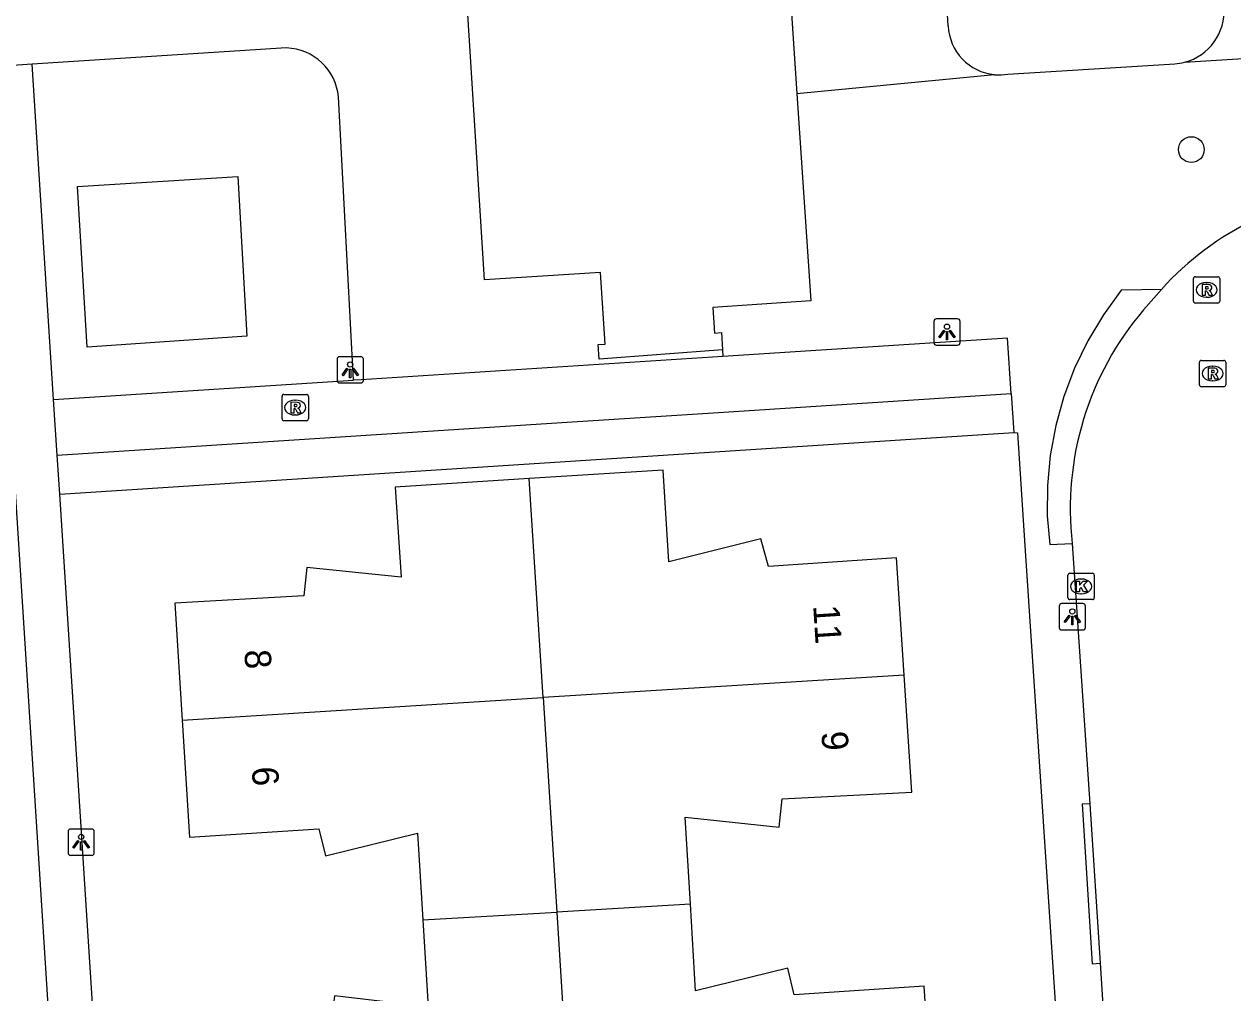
# Model space of a CAD drawing. Extents: x 159689 to 160786, y 387323 to 388339.
# Drawn here: x 160308.71 to 160354.58, y 387664.33 to 387701.1 of the extents above; entities that cross this region are included whole.
import ezdxf

# ---------------------------------------------------------------- set-up
doc = ezdxf.new("R2010")
doc.units = 0
for name, color, linetype in [('IMGEO_Boom', 7, 'Continuous'), ('IMGEO_Groenvoorziening', 7, 'Continuous'), ('IMGEO_Kolk', 7, 'Continuous'), ('IMGEO_Lichtpunt', 7, 'Continuous'), ('IMGEO_Pand', 7, 'Continuous'), ('IMGEO_Pand_nummerreeks', 7, 'Continuous'), ('IMGEO_Rijbaan_lokaal_open', 7, 'Continuous'), ('IMGEO_Rioolput', 7, 'Continuous'), ('IMGEO_Voetpad_open', 7, 'Continuous')]:
    doc.layers.add(name, color=color, linetype=linetype)

msp = doc.modelspace()

# ---------------------------------------------------------------- linework, layer by layer
at = {"layer": 'IMGEO_Boom'}
msp.add_circle((160353.01, 387696.335), 0.489, dxfattribs=at)
at = {"layer": 'IMGEO_Groenvoorziening'}
msp.add_lwpolyline([(160316.815, 387695.319), (160317.164, 387689.248), (160311.105, 387688.841), (160310.736, 387694.931), (160316.815, 387695.319)], dxfattribs=at)
at = {"layer": 'IMGEO_Kolk'}
for p, q in [((160348.327, 387679.327), (160348.327, 387680.179)), ((160348.402, 387680.253), (160349.254, 387680.253)), ((160348.815, 387680.033), (160348.84, 387680.033)), ((160349.328, 387680.179), (160349.328, 387679.327)), ((160349.254, 387679.253), (160348.402, 387679.253)), ((160348.838, 387679.473), (160348.813, 387679.473))]:
    msp.add_line(p, q, dxfattribs=at)
for points in [[(160348.327, 387679.327), (160348.327, 387680.179)], [(160348.402, 387680.253), (160349.254, 387680.253)], [(160349.328, 387680.179), (160349.328, 387679.327)], [(160348.648, 387679.953), (160348.771, 387679.953), (160348.771, 387679.802), (160348.901, 387679.953), (160349.065, 387679.953), (160348.919, 387679.802), (160349.072, 387679.553), (160348.92, 387679.553), (160348.835, 387679.717), (160348.771, 387679.65), (160348.771, 387679.553), (160348.648, 387679.553), (160348.648, 387679.953)], [(160349.254, 387679.253), (160348.402, 387679.253)]]:
    msp.add_lwpolyline(points, dxfattribs=at)
for centre, start, end in [((160348.404, 387680.177), 91.552, 178.448), ((160348.404, 387680.177), 91.552, 178.448), ((160349.252, 387680.177), 1.552, 88.448), ((160349.252, 387680.177), 1.552, 88.448), ((160348.404, 387679.329), 181.552, 268.448), ((160348.404, 387679.329), 181.552, 268.448), ((160349.252, 387679.329), 271.552, 358.448), ((160349.252, 387679.329), 271.552, 358.448)]:
    msp.add_arc(centre, 0.0765, start, end, dxfattribs=at)
for centre, major_axis, ratio, start_param, end_param in [((160348.814, 387679.753), (-0.387, 0.002), 0.722429, 4.712389, 7.853982), ((160348.839, 387679.753), (-0.39, 0.002), 0.717154, 1.570796, 4.712389)]:
    msp.add_ellipse(centre, major_axis=major_axis, ratio=ratio, start_param=start_param, end_param=end_param, dxfattribs=at)
at = {"layer": 'IMGEO_Lichtpunt'}
for p, q in [((160343.238, 387689.815), (160343.238, 387689.008)), ((160343.238, 387689.815), (160343.238, 387689.008)), ((160344.14, 387689.91), (160343.332, 387689.91)), ((160344.14, 387689.91), (160343.332, 387689.91)), ((160344.234, 387689.008), (160344.234, 387689.815)), ((160344.234, 387689.008), (160344.234, 387689.815)), ((160343.332, 387688.914), (160344.14, 387688.914)), ((160343.332, 387688.914), (160344.14, 387688.914)), ((160320.588, 387688.379), (160320.588, 387687.572)), ((160320.588, 387688.379), (160320.588, 387687.572)), ((160321.49, 387688.474), (160320.682, 387688.474)), ((160321.49, 387688.474), (160320.682, 387688.474)), ((160321.584, 387687.572), (160321.584, 387688.379)), ((160321.584, 387687.572), (160321.584, 387688.379)), ((160320.682, 387687.478), (160321.49, 387687.478)), ((160320.682, 387687.478), (160321.49, 387687.478)), ((160347.994, 387679.004), (160347.994, 387678.197)), ((160347.994, 387679.004), (160347.994, 387678.197)), ((160348.896, 387679.099), (160348.088, 387679.099)), ((160348.896, 387679.099), (160348.088, 387679.099)), ((160348.99, 387678.197), (160348.99, 387679.004)), ((160348.99, 387678.197), (160348.99, 387679.004)), ((160348.088, 387678.103), (160348.896, 387678.103)), ((160348.088, 387678.103), (160348.896, 387678.103)), ((160310.376, 387670.446), (160310.376, 387669.639)), ((160310.376, 387670.446), (160310.376, 387669.639)), ((160311.278, 387670.541), (160310.47, 387670.541)), ((160311.278, 387670.541), (160310.47, 387670.541)), ((160311.372, 387669.639), (160311.372, 387670.446)), ((160311.372, 387669.639), (160311.372, 387670.446)), ((160310.47, 387669.545), (160311.278, 387669.545)), ((160310.47, 387669.545), (160311.278, 387669.545))]:
    msp.add_line(p, q, dxfattribs=at)
for points in [[(160343.612, 387689.479), (160343.651, 387689.451), (160343.463, 387689.189), (160343.425, 387689.216), (160343.612, 387689.479)], [(160343.714, 387689.431), (160343.761, 387689.431), (160343.761, 387689.109), (160343.714, 387689.109), (160343.714, 387689.431)], [(160343.824, 387689.451), (160343.862, 387689.478), (160344.049, 387689.216), (160344.01, 387689.188), (160343.824, 387689.451)], [(160320.962, 387688.043), (160321.001, 387688.015), (160320.813, 387687.753), (160320.775, 387687.78), (160320.962, 387688.043)], [(160321.064, 387687.995), (160321.111, 387687.995), (160321.111, 387687.673), (160321.064, 387687.673), (160321.064, 387687.995)], [(160321.174, 387688.015), (160321.212, 387688.042), (160321.399, 387687.78), (160321.36, 387687.752), (160321.174, 387688.015)], [(160348.368, 387678.668), (160348.407, 387678.64), (160348.219, 387678.378), (160348.181, 387678.405), (160348.368, 387678.668)], [(160348.58, 387678.64), (160348.618, 387678.667), (160348.805, 387678.405), (160348.766, 387678.377), (160348.58, 387678.64)], [(160348.47, 387678.62), (160348.517, 387678.62), (160348.517, 387678.298), (160348.47, 387678.298), (160348.47, 387678.62)], [(160310.75, 387670.11), (160310.789, 387670.082), (160310.601, 387669.82), (160310.563, 387669.847), (160310.75, 387670.11)], [(160310.852, 387670.062), (160310.899, 387670.062), (160310.899, 387669.74), (160310.852, 387669.74), (160310.852, 387670.062)], [(160310.962, 387670.082), (160311, 387670.109), (160311.187, 387669.847), (160311.148, 387669.819), (160310.962, 387670.082)]]:
    msp.add_lwpolyline(points, dxfattribs=at)
for centre in [(160343.737, 387689.613), (160321.087, 387688.177), (160348.493, 387678.802), (160310.875, 387670.244)]:
    msp.add_circle(centre, 0.0994, dxfattribs=at)
for centre, start, end in [((160343.332, 387689.815), 90, 180), ((160343.332, 387689.815), 90, 180), ((160344.14, 387689.815), 0, 90), ((160344.14, 387689.815), 0, 90), ((160343.332, 387689.008), 180, 270), ((160343.332, 387689.008), 180, 270), ((160344.14, 387689.008), 270, 0), ((160344.14, 387689.008), 270, 360), ((160320.682, 387688.379), 90, 180), ((160320.682, 387688.379), 90, 180), ((160321.49, 387688.379), 0, 90), ((160321.49, 387688.379), 0, 90), ((160320.682, 387687.572), 180, 270), ((160320.682, 387687.572), 180, 270), ((160321.49, 387687.572), 270, 0), ((160321.49, 387687.572), 270, 360), ((160348.088, 387679.004), 90, 180), ((160348.088, 387679.004), 90, 180), ((160348.896, 387679.004), 0, 90), ((160348.896, 387679.004), 0, 90), ((160348.088, 387678.197), 180, 270), ((160348.088, 387678.197), 180, 270), ((160348.896, 387678.197), 270, 0), ((160348.896, 387678.197), 270, 360), ((160310.47, 387670.446), 90, 180), ((160310.47, 387670.446), 90, 180), ((160311.278, 387670.446), 0, 90), ((160311.278, 387670.446), 0, 90), ((160310.47, 387669.639), 180, 270), ((160310.47, 387669.639), 180, 270), ((160311.278, 387669.639), 270, 0), ((160311.278, 387669.639), 270, 360)]:
    msp.add_arc(centre, 0.0946, start, end, dxfattribs=at)
at = {"layer": 'IMGEO_Pand'}
for points in [[(160334.757, 387750.277), (160334.77, 387750.067), (160340.756, 387750.466), (160340.787, 387750), (160341.127, 387744.922), (160334.957, 387744.51), (160338.038, 387698.462)], [(160335.221, 387688.73), (160330.534, 387688.385), (160330.499, 387688.934), (160330.758, 387688.95), (160330.585, 387691.675), (160326.184, 387691.396), (160322.891, 387743.823), (160321.76, 387743.808), (160321.744, 387744.061), (160317.251, 387743.782), (160316.917, 387748.799)], [(160338.038, 387698.462), (160338.565, 387690.589), (160334.844, 387690.34), (160334.909, 387689.371), (160335.178, 387689.389), (160335.221, 387688.73)], [(160342.113, 387676.39), (160341.825, 387680.84), (160336.962, 387680.514), (160336.666, 387681.564), (160333.18, 387680.683), (160332.963, 387684.165), (160327.875, 387683.846)], [(160327.875, 387683.846), (160322.787, 387683.526), (160323.023, 387680.104), (160319.445, 387680.47), (160319.329, 387679.399), (160314.427, 387679.123), (160314.709, 387674.678)], [(160328.404, 387675.534), (160327.875, 387683.846)], [(160342.113, 387676.39), (160328.404, 387675.534)], [(160333.995, 387667.695), (160333.797, 387670.989), (160337.368, 387670.609), (160337.477, 387671.686), (160342.401, 387671.942), (160342.113, 387676.39)], [(160314.709, 387674.678), (160328.404, 387675.534)], [(160328.404, 387675.534), (160328.923, 387667.393)], [(160314.709, 387674.678), (160314.992, 387670.23), (160319.892, 387670.551), (160320.148, 387669.531), (160323.639, 387670.39), (160323.843, 387667.09)], [(160333.995, 387667.695), (160328.923, 387667.393)], [(160343.16, 387660.128), (160342.874, 387664.579), (160337.942, 387664.248), (160337.696, 387665.267), (160334.193, 387664.4), (160333.995, 387667.695)], [(160323.843, 387667.09), (160328.923, 387667.393)], [(160328.923, 387667.393), (160329.44, 387659.266)], [(160323.843, 387667.09), (160324.047, 387663.789), (160320.484, 387664.206), (160320.362, 387663.157), (160315.434, 387662.866), (160315.733, 387658.405)]]:
    msp.add_lwpolyline(points, dxfattribs=at)
at = {"layer": 'IMGEO_Rijbaan_lokaal_open'}
for points in [[(160307.332, 387699.465), (160310.545, 387649.137), (160306.196, 387648.893), (160305.351, 387661.608)], [(160351.878, 387691.025), (160351.194, 387690.247)], [(160348.492, 387681.386), (160349.163, 387671.503)], [(160349.163, 387671.503), (160349.552, 387665.446)], [(160349.552, 387665.446), (160350.062, 387657.509), (160350.161, 387655.978)]]:
    msp.add_lwpolyline(points, dxfattribs=at)
for centre, radius, start, end in [((160360.131, 387683.684), 11.046, 92.1396, 138.3478), ((160360.001, 387682.719), 11.586, 139.4777, 186.606)]:
    msp.add_arc(centre, radius, start, end, dxfattribs=at)
at = {"layer": 'IMGEO_Rioolput'}
for p, q in [((160353.164, 387691.51), (160354.016, 387691.51)), ((160353.089, 387690.584), (160353.089, 387691.436)), ((160353.577, 387691.29), (160353.602, 387691.29)), ((160354.09, 387691.436), (160354.09, 387690.584)), ((160353.6, 387690.73), (160353.575, 387690.73)), ((160354.016, 387690.51), (160353.164, 387690.51)), ((160353.392, 387688.335), (160354.244, 387688.335)), ((160353.317, 387687.409), (160353.317, 387688.261)), ((160353.805, 387688.115), (160353.83, 387688.115)), ((160354.318, 387688.261), (160354.318, 387687.409)), ((160353.828, 387687.555), (160353.803, 387687.555)), ((160318.497, 387686.116), (160318.497, 387686.968)), ((160318.572, 387687.042), (160319.424, 387687.042)), ((160319.498, 387686.968), (160319.498, 387686.116)), ((160354.244, 387687.335), (160353.392, 387687.335)), ((160318.985, 387686.822), (160319.01, 387686.822)), ((160319.424, 387686.042), (160318.572, 387686.042)), ((160319.008, 387686.262), (160318.983, 387686.262))]:
    msp.add_line(p, q, dxfattribs=at)
for points in [[(160353.164, 387691.51), (160354.016, 387691.51)], [(160353.089, 387690.584), (160353.089, 387691.436)], [(160353.678, 387691.208), (160353.426, 387691.21), (160353.426, 387690.81)], [(160353.604, 387691.129), (160353.55, 387691.129), (160353.55, 387691.048)], [(160353.55, 387691.048), (160353.602, 387691.048)], [(160354.09, 387691.436), (160354.09, 387690.584)], [(160353.426, 387690.81), (160353.55, 387690.81), (160353.55, 387690.972), (160353.561, 387690.972)], [(160353.608, 387690.943), (160353.679, 387690.81), (160353.819, 387690.81), (160353.754, 387690.936)], [(160354.016, 387690.51), (160353.164, 387690.51)], [(160353.392, 387688.335), (160354.244, 387688.335)], [(160353.317, 387687.409), (160353.317, 387688.261)], [(160353.906, 387688.033), (160353.654, 387688.035), (160353.654, 387687.635)], [(160353.832, 387687.954), (160353.778, 387687.954), (160353.778, 387687.873)], [(160353.778, 387687.873), (160353.83, 387687.873)], [(160354.318, 387688.261), (160354.318, 387687.409)], [(160353.654, 387687.635), (160353.778, 387687.635), (160353.778, 387687.797), (160353.789, 387687.797)], [(160353.836, 387687.768), (160353.907, 387687.635), (160354.047, 387687.635), (160353.982, 387687.761)], [(160318.497, 387686.116), (160318.497, 387686.968)], [(160318.572, 387687.042), (160319.424, 387687.042)], [(160319.498, 387686.968), (160319.498, 387686.116)], [(160354.244, 387687.335), (160353.392, 387687.335)], [(160319.086, 387686.74), (160318.834, 387686.742), (160318.834, 387686.342)], [(160318.834, 387686.342), (160318.958, 387686.342), (160318.958, 387686.504), (160318.969, 387686.504)], [(160319.012, 387686.661), (160318.958, 387686.661), (160318.958, 387686.58)], [(160318.958, 387686.58), (160319.01, 387686.58)], [(160319.016, 387686.475), (160319.087, 387686.342), (160319.227, 387686.342), (160319.162, 387686.468)], [(160319.424, 387686.042), (160318.572, 387686.042)]]:
    msp.add_lwpolyline(points, dxfattribs=at)
for centre, radius, start, end in [((160353.166, 387691.434), 0.0765, 91.552, 178.448), ((160353.166, 387691.434), 0.0765, 91.552, 178.448), ((160354.014, 387691.434), 0.0765, 1.552, 88.448), ((160354.014, 387691.434), 0.0765, 1.552, 88.448), ((160353.586, 387691.237), 0.19, 274.7715, 282.9687), ((160353.61, 387691.033), 0.0964, 77.0061, 93.1865), ((160353.624, 387691.09), 0.0378, 276.6634, 79.6772), ((160353.677, 387691.098), 0.109, 350.3612, 89.416), ((160353.675, 387691.098), 0.112, 277.5842, 350.9817), ((160353.166, 387690.586), 0.0765, 181.552, 268.448), ((160353.166, 387690.586), 0.0765, 181.552, 268.448), ((160353.56, 387690.919), 0.0533, 26.0293, 88.6989), ((160353.659, 387690.883), 0.108, 29.5134, 73.7905), ((160354.014, 387690.586), 0.0765, 271.552, 358.448), ((160354.014, 387690.586), 0.0765, 271.552, 358.448), ((160353.394, 387688.259), 0.0765, 91.552, 178.448), ((160353.394, 387688.259), 0.0765, 91.552, 178.448), ((160354.242, 387688.259), 0.0765, 1.552, 88.448), ((160354.242, 387688.259), 0.0765, 1.552, 88.448), ((160353.814, 387688.062), 0.19, 274.7715, 282.9687), ((160353.838, 387687.858), 0.0964, 77.0061, 93.1865), ((160353.852, 387687.915), 0.0378, 276.6634, 79.6772), ((160353.905, 387687.923), 0.109, 350.3612, 89.416), ((160353.903, 387687.923), 0.112, 277.5842, 350.9817), ((160353.394, 387687.411), 0.0765, 181.552, 268.448), ((160353.394, 387687.411), 0.0765, 181.552, 268.448), ((160353.788, 387687.744), 0.0533, 26.0293, 88.6989), ((160353.887, 387687.708), 0.108, 29.5134, 73.7905), ((160354.242, 387687.411), 0.0765, 271.552, 358.448), ((160354.242, 387687.411), 0.0765, 271.552, 358.448), ((160318.574, 387686.966), 0.0765, 91.552, 178.448), ((160318.574, 387686.966), 0.0765, 91.552, 178.448), ((160319.422, 387686.966), 0.0765, 1.552, 88.448), ((160319.422, 387686.966), 0.0765, 1.552, 88.448), ((160318.968, 387686.451), 0.0533, 26.0293, 88.6989), ((160318.994, 387686.769), 0.19, 274.7715, 282.9687), ((160319.018, 387686.565), 0.0964, 77.0061, 93.1865), ((160319.032, 387686.622), 0.0378, 276.6634, 79.6772), ((160319.085, 387686.63), 0.109, 350.3612, 89.416), ((160319.083, 387686.63), 0.112, 277.5842, 350.9817), ((160319.067, 387686.415), 0.108, 29.5134, 73.7905), ((160318.574, 387686.118), 0.0765, 181.552, 268.448), ((160318.574, 387686.118), 0.0765, 181.552, 268.448), ((160319.422, 387686.118), 0.0765, 271.552, 358.448), ((160319.422, 387686.118), 0.0765, 271.552, 358.448)]:
    msp.add_arc(centre, radius, start, end, dxfattribs=at)
for centre, major_axis, ratio, start_param, end_param in [((160353.576, 387691.01), (-0.387, 0.002), 0.722429, 4.712389, 7.853982), ((160353.601, 387691.01), (-0.39, 0.002), 0.717154, 1.570796, 4.712389), ((160353.804, 387687.835), (-0.387, 0.002), 0.722429, 4.712389, 7.853982), ((160353.829, 387687.835), (-0.39, 0.002), 0.717154, 1.570796, 4.712389), ((160318.984, 387686.542), (-0.387, 0.002), 0.722429, 4.712389, 7.853982), ((160319.009, 387686.542), (-0.39, 0.002), 0.717154, 1.570796, 4.712389)]:
    msp.add_ellipse(centre, major_axis=major_axis, ratio=ratio, start_param=start_param, end_param=end_param, dxfattribs=at)
at = {"layer": 'IMGEO_Voetpad_open'}
for points in [[(160343.782, 387701.036), (160342.442, 387723.647), (160341.574, 387736.998)], [(160318.672, 387700.194), (160309.013, 387699.573)], [(160352.754, 387699.654), (160358.2, 387699.993)], [(160309.013, 387699.573), (160307.332, 387699.465)], [(160309.83, 387686.843), (160309.013, 387699.573)], [(160346.046, 387699.198), (160352.384, 387699.593)], [(160338.038, 387698.462), (160345.545, 387699.18)], [(160321.205, 387687.577), (160320.639, 387698.337)], [(160351.878, 387691.025), (160350.349, 387690.994), (160349.672, 387690.064), (160349.08, 387689.078), (160348.579, 387688.043), (160348.172, 387686.967), (160347.864, 387685.859), (160347.655, 387684.727), (160347.548, 387683.582), (160347.544, 387682.432), (160347.635, 387681.347), (160348.492, 387681.386)], [(160346.172, 387687.081), (160346.029, 387689.179), (160335.233, 387688.482)], [(160335.233, 387688.482), (160321.506, 387687.596), (160321.205, 387687.577)], [(160335.221, 387688.73), (160335.233, 387688.482)], [(160309.83, 387686.843), (160321.205, 387687.577)], [(160309.965, 387684.731), (160329.119, 387685.974), (160335.067, 387686.36), (160346.172, 387687.081)], [(160346.172, 387687.081), (160346.268, 387685.591)], [(160309.965, 387684.731), (160309.83, 387686.843)], [(160310.06, 387683.259), (160346.268, 387685.591)], [(160346.268, 387685.591), (160346.407, 387685.587), (160346.692, 387681.293), (160348.666, 387651.599)], [(160310.06, 387683.259), (160309.965, 387684.731)], [(160312.24, 387649.301), (160310.06, 387683.259)], [(160349.163, 387671.503), (160348.862, 387671.484), (160349.252, 387665.427), (160349.552, 387665.446)]]:
    msp.add_lwpolyline(points, dxfattribs=at)
for centre, radius, start, end in [((160352.241, 387701.602), 2.015, 284.7581, 3.8081), ((160345.727, 387701.119), 1.947, 182.4307, 264.6252), ((160318.595, 387698.142), 2.053, 5.4397, 87.8557), ((160352.235, 387701.648), 2.06, 274.1403, 284.5834), ((160345.725, 387701.142), 1.971, 264.7496, 279.3657)]:
    msp.add_arc(centre, radius, start, end, dxfattribs=at)

# ---------------------------------------------------------------- texts
at = {"layer": 'IMGEO_Pand_nummerreeks'}
for s, rotation, p in [('11', 273.7038, (160338.656, 387679.024)), ('8', 273.6353, (160317.065, 387677.33)), ('9', 273.7038, (160338.966, 387674.229)), ('6', 273.6353, (160317.348, 387672.887))]:
    msp.add_text(s, height=1, rotation=rotation, dxfattribs=at).set_placement(p)

doc.saveas('drawing.dxf')
